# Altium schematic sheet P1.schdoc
size 297 x 209 mm; Symbol: Drawing-Symbol_A4; Company: 嘉立创EDA; Version: V1.0; Page Size: A4; @Project Name: 磁编码; @Update Date: 2026-07-21; @Create Date: 2026-07-21; Device: Drawing-Symbol_A4; @Board Name: Board1; @Page Name: P1; @Create Time: 23:07:32; @Page Count: 1; @Page No: 1; @Schematic Name: Schematic1; @Update Time: 23:07:32; @Assembly Variant: Basic; Border: 1; Title Block Position: 3; Size: A4; Width: 1170; Height: 825; Region Start: 1; X Region Count: 6; Y Region Count: 4; Blade Width: 10
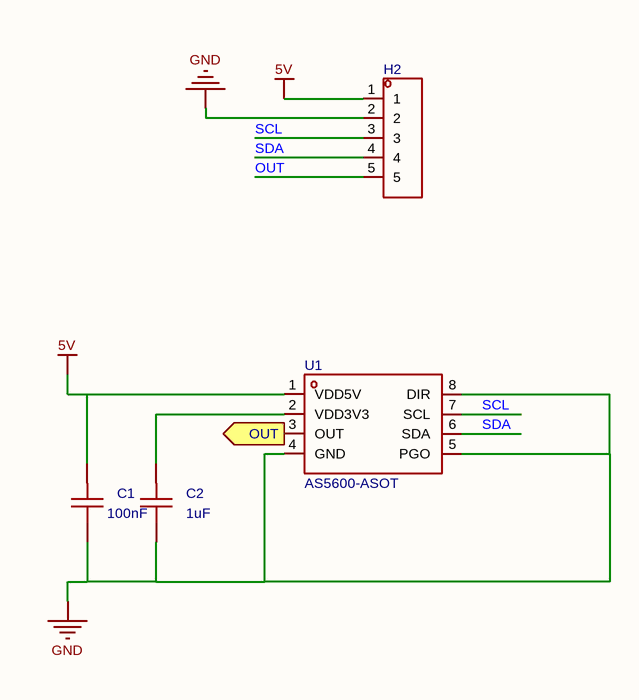
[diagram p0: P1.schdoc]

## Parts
C1  100nF  [C0603]
C2  1uF  [C0603]
H2  (no value)  [HDR-TH_5P-P2.54-V-M]
U1  AS5600-ASOT  [SOIC-8_L5.0-W4.0-P1.27-LS6.0-BL]

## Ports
OUT (out)

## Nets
5V: C1.2 H2.1 U1.1(VDD5V)
GND: C1.1 C2.1 H2.2 U1.4(GND) U1.5(PGO) U1.8(DIR)
OUT: U1.3(OUT) ; port OUT
OUT: H2.5  [a separate net that carries the same name]
SCL: H2.3 U1.7(SCL)
SDA: H2.4 U1.6(SDA)
NetC2_2: C2.2 U1.2(VDD3V3)

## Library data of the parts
C1 C2 = CAP_0603: Symbol: Capacitance; ConvertToPcb: yes; ModelId: ac125912035d415993ca9572d50418b10819f05c4eef4c71ace90d822a990e87; ModelName: C0603_L1.6-W0.8-H0.8; ModelTransform: 62.992,31.496,0,0,0,0,0,0,0
H2 = HDR-M_2.54_1x5P: Symbol: MTP125-1105S1; ConvertToPcb: yes; ModelId: 47d466e4a34f4fc5bc626cf773a24dd50819f05c4eef4c71ace90d822a990e87; ModelName: HDR-TH_5P-P2.54-M-LI-1X5P; ModelTransform: 499.999,100,0,0,0,0,0,0,-118.11
U1 = AS5600-ASOT: 旋转角度范围:0°~360°;; Manufacturer: ams(艾迈斯半导体); AddInBom: yes; ModelId: 7abc64c95a1a4a04a4ef38f9097c870b0819f05c4eef4c71ace90d822a990e87; ModelTransform: 192.913,236.22,0,0,0,0,0,0,0; Voltage - Supply: 5V；3.3V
